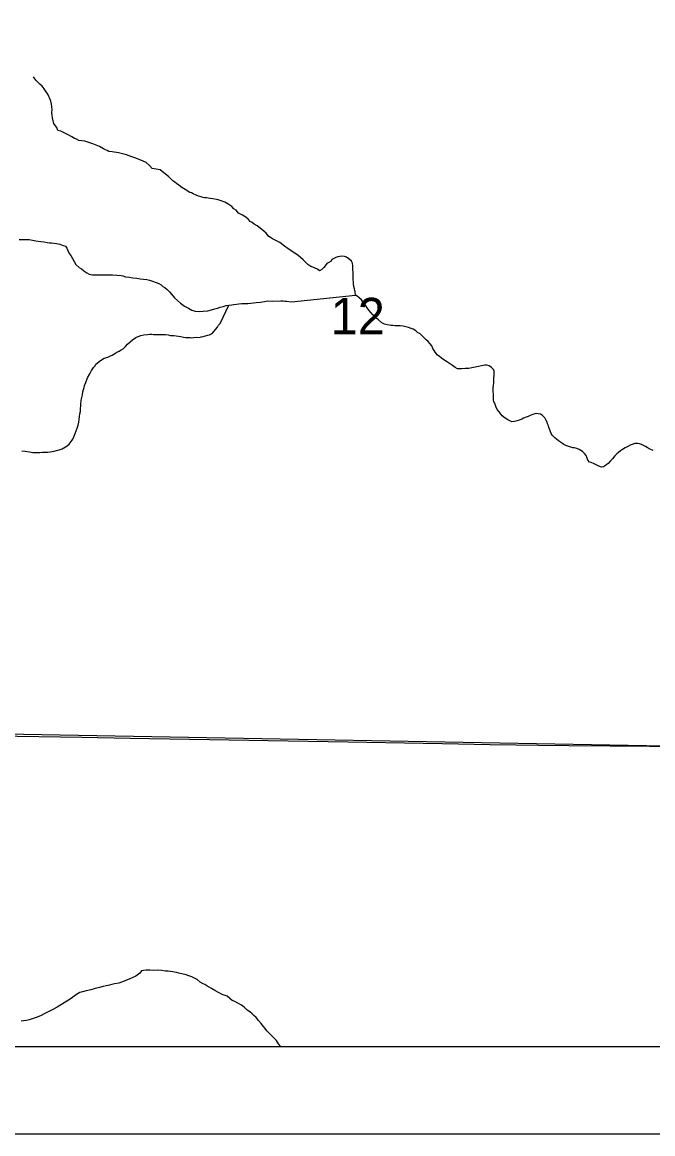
# Model space of a CAD drawing. Extents: x 0 to 34, y 0 to 22.
# Drawn here: x 5.73 to 6.454, y 14 to 15.275 of the extents above; entities that cross this region are included whole.
import ezdxf

# ---------------------------------------------------------------- set-up
doc = ezdxf.new("R2010")
doc.units = 0
for name, color, linetype in [('GM_X_County_Text', 7, 'Continuous'), ('GM_X_Minor_River', 7, 'Continuous'), ('GM_X_Rail_Line_Text', 7, 'Continuous'), ('GM_X_Section', 7, 'Continuous'), ('GM_X_Section_Text', 7, 'Continuous'), ('GM_X_Township_Road', 7, 'Continuous'), ('SH_Cut_Line', 7, 'Continuous'), ('SH_Data', 7, 'Continuous')]:
    doc.layers.add(name, color=color, linetype=linetype)

msp = doc.modelspace()

# ---------------------------------------------------------------- linework, layer by layer
at = {"layer": 'GM_X_County_Text'}
msp.add_lwpolyline([(2.1, 14.1), (6.615, 14.1)], dxfattribs=at)
at = {"layer": 'GM_X_Minor_River'}
for points in [[(6.0525, 15.0023), (6.0496, 15.005), (6.0466, 15.0077), (6.0354, 15.0152), (6.0313, 15.0183), (6.0257, 15.0223), (6.0204, 15.0251), (6.0174, 15.0266), (6.0152, 15.0282), (6.0133, 15.0294), (6.0115, 15.031), (6.01, 15.0329), (6.0074, 15.0352), (6.0033, 15.0388), (5.9999, 15.0415), (5.9962, 15.0435), (5.9939, 15.0451), (5.9917, 15.0466), (5.9899, 15.0486), (5.9869, 15.0513), (5.9831, 15.0537), (5.9805, 15.0549), (5.9783, 15.0561), (5.9757, 15.0596), (5.9731, 15.0611), (5.9705, 15.0635), (5.9671, 15.0658), (5.9626, 15.0686), (5.9585, 15.0702), (5.9551, 15.0711), (5.9532, 15.0715), (5.949, 15.0723), (5.946, 15.0728), (5.9434, 15.0732), (5.9415, 15.0737), (5.9392, 15.0737), (5.9373, 15.0741), (5.9354, 15.0746), (5.9324, 15.0754), (5.9298, 15.0766), (5.9264, 15.0782), (5.9245, 15.0794), (5.9226, 15.0798), (5.917, 15.083), (5.9151, 15.0842), (5.9133, 15.0853), (5.9099, 15.0881), (5.9073, 15.0901), (5.9051, 15.0916), (5.9028, 15.0932), (5.9002, 15.0959), (5.898, 15.0979), (5.8946, 15.1006), (5.8883, 15.1057), (5.8792, 15.1074), (5.8763, 15.1105), (5.8722, 15.1141), (5.8681, 15.1161), (5.865, 15.1173), (5.8632, 15.1181), (5.8605, 15.1189), (5.856, 15.1205), (5.8496, 15.123), (5.8406, 15.1251), (5.8334, 15.1264), (5.8296, 15.1269), (5.8277, 15.1277), (5.8258, 15.1285), (5.8232, 15.1297), (5.8187, 15.1324), (5.8112, 15.1356), (5.8021, 15.1385), (5.795, 15.1395), (5.7923, 15.1407), (5.7901, 15.1418), (5.7871, 15.1434), (5.7837, 15.1454), (5.7796, 15.1474), (5.7743, 15.1502), (5.7709, 15.151), (5.7699, 15.1541), (5.7684, 15.156), (5.7662, 15.1588), (5.7648, 15.1652), (5.7645, 15.1683), (5.7642, 15.171), (5.7643, 15.1748), (5.764, 15.1778), (5.7637, 15.1812), (5.763, 15.1843), (5.7623, 15.1862), (5.7612, 15.1881), (5.7605, 15.19), (5.7594, 15.1924), (5.7575, 15.1951), (5.7553, 15.1985), (5.7528, 15.2016), (5.7502, 15.204), (5.7476, 15.2067), (5.7457, 15.2086), (5.7431, 15.2125)], [(5.7266, 15.0256), (5.7304, 15.0258), (5.7342, 15.0258), (5.738, 15.0257), (5.7418, 15.0252), (5.7456, 15.0243), (5.7516, 15.0234), (5.7554, 15.023), (5.7588, 15.0225), (5.7615, 15.0221), (5.7637, 15.022), (5.7664, 15.0216), (5.7694, 15.0211), (5.7732, 15.0203), (5.7769, 15.019), (5.7796, 15.0182), (5.7814, 15.0159), (5.7825, 15.0132), (5.7839, 15.0098), (5.7858, 15.0074), (5.7898, 15.0005), (5.7916, 14.997), (5.7953, 14.9935), (5.798, 14.9923), (5.8006, 14.99), (5.8043, 14.9876), (5.8069, 14.986), (5.8107, 14.9852), (5.8137, 14.9851), (5.8156, 14.9851), (5.8198, 14.9854), (5.824, 14.9853), (5.8289, 14.9851), (5.8335, 14.9854), (5.8437, 14.9844), (5.8456, 14.984), (5.8486, 14.9831), (5.8528, 14.9827), (5.8569, 14.9818), (5.8615, 14.9813), (5.8656, 14.9808), (5.8694, 14.9804), (5.8732, 14.9799), (5.8762, 14.9791), (5.8796, 14.9779), (5.8838, 14.9766), (5.8868, 14.9754), (5.8894, 14.9738), (5.8916, 14.9719), (5.8939, 14.9707), (5.8965, 14.9683), (5.8991, 14.9656), (5.9013, 14.9629), (5.905, 14.959), (5.9117, 14.9528), (5.9162, 14.9492), (5.921, 14.9469), (5.9248, 14.9449), (5.9285, 14.9436), (5.9331, 14.9431), (5.9377, 14.9434), (5.943, 14.9441), (5.9472, 14.9451), (5.951, 14.9461), (5.9541, 14.9472), (5.9571, 14.9483), (5.9609, 14.9489), (5.964, 14.95), (5.9674, 14.9503), (5.9705, 14.951), (5.9731, 14.9513), (5.9762, 14.9516), (5.9789, 14.9519), (5.9823, 14.9522), (5.9857, 14.9522), (5.9891, 14.9525)], [(6.2709, 14.8588), (6.2713, 14.861), (6.2714, 14.8629), (6.2714, 14.8648), (6.2715, 14.8671), (6.2719, 14.8697), (6.2719, 14.8716), (6.272, 14.8747), (6.2709, 14.8766), (6.2687, 14.8789), (6.2661, 14.8809), (6.2631, 14.8817), (6.2612, 14.8818), (6.2501, 14.8794), (6.2463, 14.8787), (6.2429, 14.878), (6.2387, 14.8778), (6.2349, 14.8775), (6.2315, 14.8775), (6.2296, 14.8776), (6.2269, 14.8788), (6.224, 14.8811), (6.2206, 14.8835), (6.2172, 14.8859), (6.2142, 14.8878), (6.2112, 14.8898), (6.2086, 14.8918), (6.2068, 14.8933), (6.2042, 14.8964), (6.2031, 14.8984), (6.2016, 14.9007), (6.2002, 14.9037), (6.198, 14.9065), (6.1961, 14.9088), (6.1939, 14.9107), (6.192, 14.9127), (6.1894, 14.915), (6.1868, 14.9174), (6.1839, 14.9193), (6.182, 14.9209), (6.179, 14.9229), (6.1767, 14.9237), (6.1734, 14.9249), (6.1703, 14.9257), (6.1673, 14.9262), (6.1639, 14.9266), (6.1605, 14.9267), (6.1578, 14.9268), (6.1556, 14.9272), (6.1537, 14.9273), (6.1518, 14.9277), (6.1491, 14.9278), (6.1461, 14.9286), (6.1427, 14.9302), (6.139, 14.9337), (6.1372, 14.9353), (6.1353, 14.9376), (6.1327, 14.9395), (6.1305, 14.9415), (6.1279, 14.9446), (6.126, 14.9473), (6.1242, 14.9504), (6.122, 14.9531), (6.1194, 14.9566), (6.1165, 14.9593), (6.1146, 14.9609), (6.1127, 14.9621), (6.1121, 14.9659), (6.1114, 14.9693), (6.1107, 14.972), (6.1104, 14.9747), (6.1104, 14.9766), (6.1101, 14.9804), (6.1099, 14.9853), (6.1099, 14.988), (6.1096, 14.9914), (6.1097, 14.9956), (6.1094, 14.9986), (6.1079, 15.0009), (6.105, 15.0037), (6.1024, 15.0056), (6.1001, 15.0064), (6.0971, 15.0065), (6.0948, 15.0062), (6.0925, 15.0059), (6.0902, 15.0052), (6.0856, 15.003), (6.0848, 15.0011), (6.0821, 14.9993), (6.0798, 14.9982), (6.0778, 14.9956), (6.0763, 14.9937), (6.0739, 14.9915), (6.0712, 14.99), (6.069, 14.9916), (6.0664, 14.9928), (6.0637, 14.994), (6.0615, 14.9948), (6.0581, 14.9972), (6.0548, 15.0003), (6.0525, 15.0023)], [(5.9891, 14.9525), (5.9925, 14.9528), (5.9986, 14.9534), (6.0036, 14.954), (6.0082, 14.9547), (6.012, 14.9553), (6.0169, 14.9552), (6.0271, 14.9554), (6.0298, 14.9553), (6.0317, 14.9552), (6.0336, 14.9552), (6.0393, 14.9543), (6.1127, 14.9621)], [(5.7954, 14.8195), (5.7959, 14.8229), (5.7963, 14.8259), (5.7968, 14.8286), (5.7968, 14.8309), (5.7978, 14.8415), (5.7983, 14.8445), (5.7991, 14.8475), (5.7996, 14.8509), (5.8004, 14.8536), (5.8012, 14.8562), (5.8017, 14.8585), (5.8029, 14.8619), (5.8049, 14.8671), (5.8077, 14.8716), (5.8096, 14.8754), (5.812, 14.8788), (5.8136, 14.881), (5.8147, 14.8829), (5.8198, 14.8869), (5.824, 14.8895), (5.8282, 14.8909), (5.8305, 14.892), (5.8332, 14.8931), (5.8363, 14.8949), (5.8386, 14.8964), (5.8413, 14.8978), (5.8436, 14.8993), (5.8459, 14.9004), (5.8486, 14.903), (5.851, 14.9056), (5.8541, 14.9085), (5.8568, 14.9108), (5.8606, 14.9133), (5.8633, 14.9144), (5.8664, 14.9155), (5.8698, 14.9165), (5.874, 14.9168), (5.8767, 14.9171), (5.879, 14.9171), (5.8808, 14.917), (5.8884, 14.9168), (5.8915, 14.9168), (5.8945, 14.9167), (5.8975, 14.9163), (5.9002, 14.9158), (5.904, 14.9157), (5.9066, 14.9153), (5.9093, 14.9148), (5.9123, 14.9144), (5.9153, 14.9139), (5.918, 14.9135), (5.9202, 14.9134), (5.9229, 14.9134), (5.9248, 14.9129), (5.9267, 14.9133), (5.9305, 14.9136), (5.9335, 14.9135), (5.9355, 14.9142), (5.9377, 14.9145), (5.9404, 14.9152), (5.9431, 14.9159), (5.945, 14.9166), (5.9481, 14.9181), (5.9504, 14.9207), (5.952, 14.9226), (5.9543, 14.9252), (5.9555, 14.9274), (5.9571, 14.9293), (5.9674, 14.9503)], [(6.4544, 14.7837), (6.4518, 14.7849), (6.4499, 14.7857), (6.4476, 14.7873), (6.4454, 14.7885), (6.4431, 14.7893), (6.4409, 14.7905), (6.4386, 14.7913), (6.4367, 14.7917), (6.4333, 14.7918), (6.4302, 14.7907), (6.4279, 14.7897), (6.4253, 14.7882), (6.4222, 14.7868), (6.4191, 14.7849), (6.4168, 14.7835), (6.4145, 14.7816), (6.4125, 14.7801), (6.4102, 14.7775), (6.4075, 14.7742), (6.4055, 14.772), (6.4028, 14.769), (6.3997, 14.7664), (6.3974, 14.7649), (6.3951, 14.7646), (6.3921, 14.7658), (6.3898, 14.767), (6.3865, 14.7686), (6.3831, 14.7698), (6.3812, 14.7703), (6.3793, 14.7726), (6.3786, 14.7749), (6.3776, 14.7779), (6.3757, 14.7803), (6.3731, 14.7826), (6.3712, 14.7838), (6.3694, 14.785), (6.3667, 14.7862), (6.3641, 14.787), (6.3622, 14.787), (6.3599, 14.7875), (6.3566, 14.7887), (6.3543, 14.7895), (6.352, 14.7907), (6.3502, 14.7919), (6.3479, 14.7935), (6.3457, 14.795), (6.3435, 14.7966), (6.3416, 14.7982), (6.3386, 14.8013), (6.3372, 14.8032), (6.3364, 14.8051), (6.3357, 14.8074), (6.3347, 14.8101), (6.3343, 14.812), (6.3332, 14.8143), (6.3325, 14.8162), (6.3311, 14.8189), (6.33, 14.8212), (6.327, 14.8244), (6.3252, 14.8255), (6.3195, 14.8261), (6.3172, 14.8254), (6.3149, 14.8246), (6.313, 14.8239), (6.311, 14.8228), (6.3087, 14.8218), (6.3057, 14.8207), (6.3037, 14.8196), (6.3015, 14.8189), (6.2984, 14.8178), (6.295, 14.8171), (6.2923, 14.8168), (6.2897, 14.8176), (6.2874, 14.8188), (6.2844, 14.8208), (6.2811, 14.8236), (6.2774, 14.8282), (6.2752, 14.8309), (6.2737, 14.8344), (6.273, 14.837), (6.2716, 14.8394), (6.2709, 14.8417), (6.2709, 14.8443), (6.271, 14.8481), (6.2707, 14.8519), (6.2708, 14.8553), (6.2709, 14.8588)], [(5.7297, 14.7834), (5.7334, 14.783), (5.7384, 14.7821), (5.7421, 14.7816), (5.7463, 14.7815), (5.7501, 14.7814), (5.7535, 14.7817), (5.757, 14.782), (5.7596, 14.782), (5.7623, 14.7823), (5.7646, 14.7826), (5.7668, 14.7829), (5.7695, 14.7836), (5.7726, 14.7847), (5.776, 14.7858), (5.778, 14.7868), (5.7799, 14.7879), (5.7818, 14.789), (5.7841, 14.7909), (5.7861, 14.7939), (5.7881, 14.7969), (5.7893, 14.7995), (5.7909, 14.8033), (5.7921, 14.8063), (5.7933, 14.8093), (5.7941, 14.8127), (5.795, 14.8161), (5.7954, 14.8195)], [(5.9307, 14.1768), (5.9277, 14.1783), (5.9247, 14.1799), (5.9213, 14.1812), (5.9183, 14.1824), (5.91, 14.1841), (5.9073, 14.1849), (5.9047, 14.1853), (5.9028, 14.1858), (5.9001, 14.1862), (5.8975, 14.1867), (5.8945, 14.1867), (5.8903, 14.1872), (5.8858, 14.1877), (5.8808, 14.1874), (5.8766, 14.1875), (5.8725, 14.1876), (5.8694, 14.1873), (5.8671, 14.187), (5.8652, 14.1844), (5.8605, 14.1807), (5.8536, 14.1778), (5.8471, 14.1749), (5.841, 14.1728), (5.836, 14.1718), (5.833, 14.1711), (5.8303, 14.1704), (5.8265, 14.1697), (5.8231, 14.169), (5.8188, 14.1676), (5.8139, 14.1666), (5.8089, 14.1652), (5.8036, 14.1638), (5.7994, 14.1628), (5.7963, 14.1621), (5.7944, 14.161), (5.7925, 14.1599), (5.7898, 14.158), (5.7863, 14.1551), (5.7701, 14.1452), (5.7651, 14.1427), (5.7605, 14.1401), (5.7559, 14.1379), (5.7509, 14.1354), (5.7459, 14.1332), (5.7413, 14.1318), (5.7379, 14.1308), (5.7348, 14.1301), (5.7314, 14.1294), (5.7287, 14.1291)], [(6.0267, 14.1), (6.0261, 14.1008), (6.0242, 14.1031), (6.022, 14.107), (6.0191, 14.1097), (6.0165, 14.1124), (6.0146, 14.1143), (6.0128, 14.1163), (6.0109, 14.1182), (6.0091, 14.1206), (6.0069, 14.1229), (6.0043, 14.1264), (6.0013, 14.1299), (5.9988, 14.1333), (5.9961, 14.1357), (5.9939, 14.1376), (5.9913, 14.14), (5.9894, 14.1412), (5.9876, 14.1427), (5.985, 14.1451), (5.9816, 14.1474), (5.9775, 14.1498), (5.9741, 14.1518), (5.9711, 14.153), (5.9685, 14.155), (5.9652, 14.1577), (5.9595, 14.1597), (5.9554, 14.1621), (5.9513, 14.1645), (5.9475, 14.1665), (5.9445, 14.1681), (5.9419, 14.1696), (5.9397, 14.1712), (5.9378, 14.172), (5.9344, 14.174), (5.9307, 14.1768)]]:
    msp.add_lwpolyline(points, dxfattribs=at)
at = {"layer": 'GM_X_Rail_Line_Text'}
msp.add_lwpolyline([(5.6017, 14.1), (6.6103, 14.1), (6.615, 14.4419), (5.6049, 14.4601)], close=True, dxfattribs=at)
at = {"layer": 'GM_X_Section'}
msp.add_lwpolyline([(5.6179, 15.4598), (6.6291, 15.4393), (6.615, 14.4419), (5.6049, 14.4601)], close=True, dxfattribs=at)
at = {"layer": 'GM_X_Township_Road'}
msp.add_lwpolyline([(5.6052, 14.4578), (5.6904, 14.4564), (5.7246, 14.4559), (5.7985, 14.4548), (5.8539, 14.4537), (5.9676, 14.452), (6.0124, 14.4511), (6.1044, 14.4496), (6.1902, 14.4479), (6.2125, 14.4475), (6.2672, 14.4465), (6.2971, 14.4461), (6.3226, 14.4459), (6.3574, 14.4455), (6.4049, 14.4449), (6.4276, 14.4449), (6.45, 14.4447), (6.4749, 14.4441)], dxfattribs=at)
at = {"layer": 'SH_Cut_Line'}
msp.add_lwpolyline([(2.1, 16.5239), (2.1, 14.1), (8.9, 14.1), (8.9, 16.3981)], dxfattribs=at)
at = {"layer": 'SH_Data'}
for p, q in [((2.1, 14.1), (8.9, 14.1)), ((2, 14), (9, 14))]:
    msp.add_line(p, q, dxfattribs=at)

# ---------------------------------------------------------------- texts
at = {"layer": 'GM_X_Section_Text'}
msp.add_text('12', height=0.04186, rotation=0, dxfattribs=at).set_placement((6.0841, 14.917))

doc.saveas('drawing.dxf')
